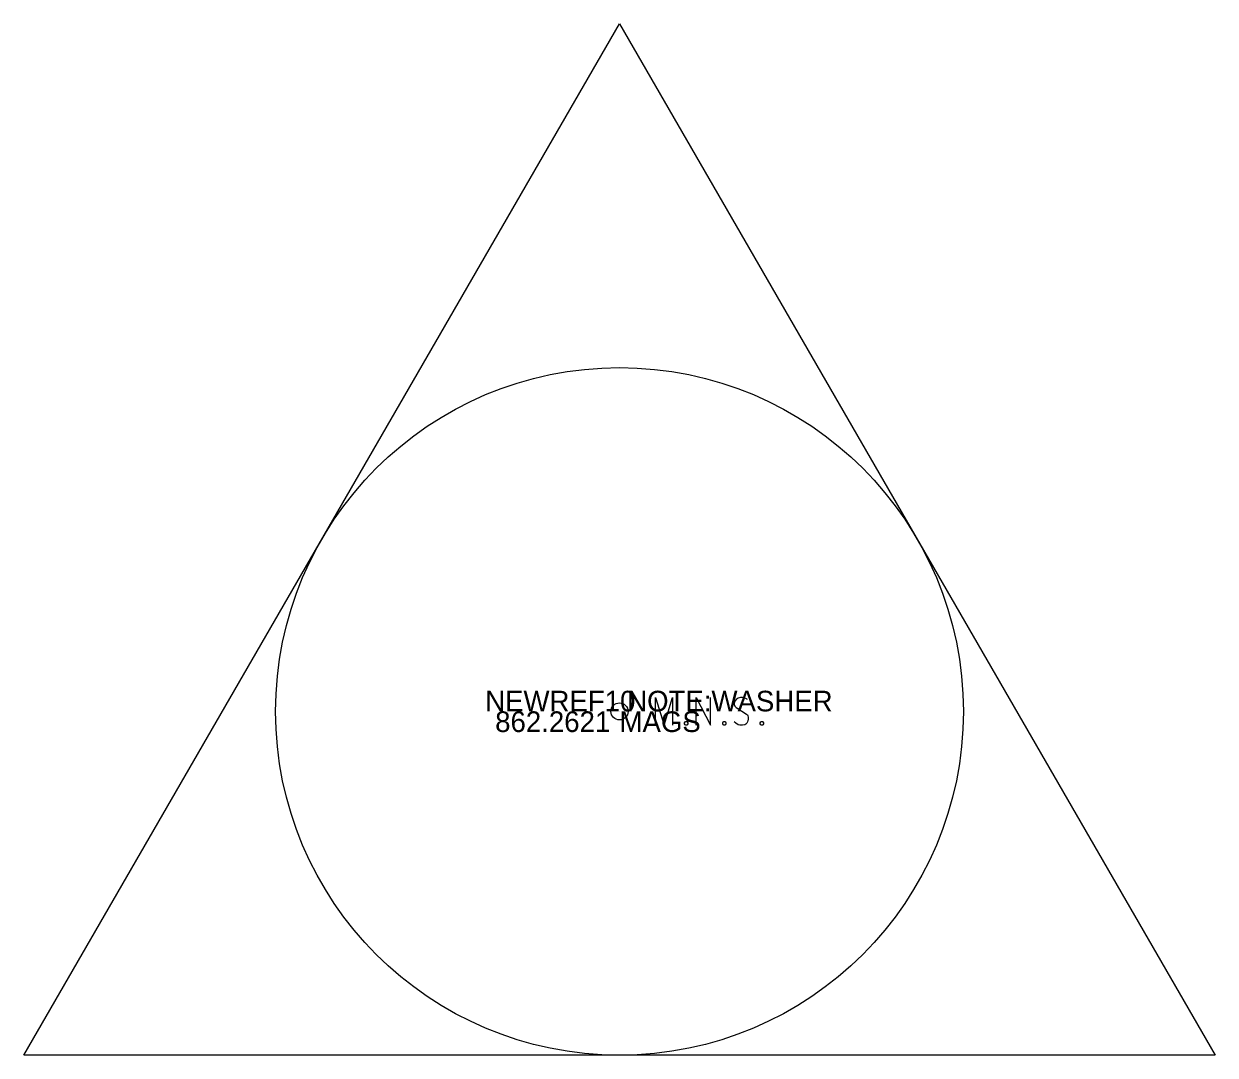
# Model space of a CAD drawing. Extents: x 1785178 to 1804417, y 483851 to 522189.
# Drawn here: x 1800353.923 to 1800357.387, y 494968.434 to 494971.434 of the extents above; entities that cross this region are included whole.
import ezdxf

# ---------------------------------------------------------------- set-up
doc = ezdxf.new("R2010")
doc.units = 0
for name, color, linetype in [('SV_Control_Point', 7, 'Continuous'), ('SV_P_Control_Cells_Set', 7, 'Continuous'), ('SV_X_Text_Comment', 7, 'Continuous'), ('SV_X_Text_Description', 7, 'Continuous'), ('SV_X_Text_Elevation', 7, 'Continuous'), ('SV_X_Text_Name', 7, 'Continuous')]:
    doc.layers.add(name, color=color, linetype=linetype)

msp = doc.modelspace()

# ---------------------------------------------------------------- linework, layer by layer
at = {"layer": 'SV_Control_Point'}
for p, q in [((1800353.9229, 494968.4344), (1800355.655, 494971.4344)), ((1800355.655, 494971.4344), (1800357.3871, 494968.4344)), ((1800355.655, 494969.4344), (1800355.655, 494969.4344)), ((1800357.3871, 494968.4344), (1800353.9229, 494968.4344))]:
    msp.add_line(p, q, dxfattribs=at)
msp.add_circle((1800355.655, 494969.4344), 1, dxfattribs=at)
at = {"layer": 'SV_P_Control_Cells_Set'}
for points in [[(1800355.7595, 494969.3944), (1800355.7595, 494969.4744), (1800355.7849, 494969.3944), (1800355.8091, 494969.4744), (1800355.8091, 494969.3944)], [(1800355.878, 494969.3944), (1800355.878, 494969.4744), (1800355.9194, 494969.3944), (1800355.9194, 494969.4744)], [(1800356.0268, 494969.4687), (1800356.0257, 494969.47), (1800356.0241, 494969.4712), (1800356.0191, 494969.4731), (1800356.013, 494969.4744), (1800356.0086, 494969.4744), (1800356.007, 494969.4744), (1800355.9998, 494969.4725), (1800355.9938, 494969.4687), (1800355.9899, 494969.4637), (1800355.9888, 494969.4586), (1800355.9888, 494969.4548), (1800355.9899, 494969.4498), (1800355.9943, 494969.4454), (1800356.0246, 494969.4265), (1800356.0274, 494969.424), (1800356.0285, 494969.4215), (1800356.0296, 494969.4177), (1800356.0296, 494969.4139), (1800356.029, 494969.4101), (1800356.0285, 494969.4076), (1800356.0274, 494969.4045), (1800356.0263, 494969.4019), (1800356.0252, 494969.4001), (1800356.0235, 494969.3982), (1800356.0219, 494969.3969), (1800356.0197, 494969.3956), (1800356.018, 494969.395), (1800356.013, 494969.3944), (1800356.0053, 494969.3944), (1800356.0004, 494969.3956), (1800355.9932, 494969.4001), (1800355.9888, 494969.4038)], [(1800355.8477, 494969.4051), (1800355.8505, 494969.4051), (1800355.8521, 494969.4038), (1800355.8538, 494969.4013), (1800355.8538, 494969.3982), (1800355.8521, 494969.3956), (1800355.8505, 494969.3944), (1800355.8477, 494969.3944), (1800355.8461, 494969.3956), (1800355.8444, 494969.3982), (1800355.8444, 494969.4013), (1800355.8461, 494969.4038), (1800355.8477, 494969.4051)], [(1800355.9585, 494969.4051), (1800355.9612, 494969.4051), (1800355.9629, 494969.4038), (1800355.9645, 494969.4013), (1800355.9645, 494969.3982), (1800355.9629, 494969.3956), (1800355.9612, 494969.3944), (1800355.9585, 494969.3944), (1800355.9568, 494969.3956), (1800355.9552, 494969.3982), (1800355.9552, 494969.4013), (1800355.9568, 494969.4038), (1800355.9585, 494969.4051)], [(1800356.0676, 494969.4051), (1800356.0704, 494969.4051), (1800356.072, 494969.4038), (1800356.0737, 494969.4013), (1800356.0737, 494969.3982), (1800356.072, 494969.3956), (1800356.0704, 494969.3944), (1800356.0676, 494969.3944), (1800356.066, 494969.3956), (1800356.0643, 494969.3982), (1800356.0643, 494969.4013), (1800356.066, 494969.4038), (1800356.0676, 494969.4051)]]:
    msp.add_lwpolyline(points, dxfattribs=at)
msp.add_circle((1800355.655, 494969.4344), 0.0249, dxfattribs=at)

# ---------------------------------------------------------------- texts
at = {"layer": 'SV_X_Text_Comment'}
msp.add_text('MAGS', height=0.06, dxfattribs=at).set_placement((1800355.655, 494969.3744))
at = {"layer": 'SV_X_Text_Description'}
msp.add_text(' NOTE:WASHER', height=0.06, dxfattribs=at).set_placement((1800355.655, 494969.4344))
at = {"layer": 'SV_X_Text_Elevation'}
msp.add_text('862.2621', height=0.06, dxfattribs=at).set_placement((1800355.2935, 494969.3744))
at = {"layer": 'SV_X_Text_Name'}
msp.add_text('NEWREF10', height=0.06, dxfattribs=at).set_placement((1800355.2644, 494969.4344))

doc.saveas('drawing.dxf')
